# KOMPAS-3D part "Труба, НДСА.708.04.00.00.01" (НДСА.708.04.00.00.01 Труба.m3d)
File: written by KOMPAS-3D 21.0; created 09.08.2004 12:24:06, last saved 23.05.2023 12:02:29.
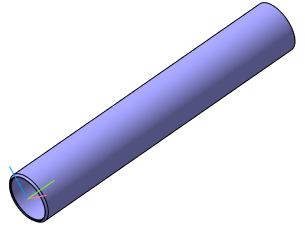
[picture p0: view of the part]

Document properties: Полное имя файла: C:\Users\s.pischagina\Desktop\PLM\НДСА.708.04.00.00.01 Труба.m3d; Автор: Устинов А.В.; Организация: Эсто-вакуум

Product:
- Part/product: Труба  | designation НДСА.708.04.00.00.01
    Материал: Труба$d180х10 ГОСТ 8732-78;20 ГОСТ 8731-74$ (density 7859 kg/m3)
    Масса: 46.57347
    additional columns: <item xmlns="http://appius.ru/pdm" xmlns:xs="http://www.w3.org/2001/XMLSchema" x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; <item xmlns="http://appius.ru/pdm" xmlns:xs="http://www.w3.org/2001/XMLSchema" x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; <item xmlns="http://appius.ru/pdm" xmlns:xs="http://www.w3.org/2001/XMLSchema" x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; <item xmlns="http://appius.ru/pdm" xmlns:xs="http://www.w3.org/2001/XMLSchema" x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; <item xmlns="http://appius.ru/pdm" xmlns:xs="http://www.w3.org/2001/XMLSchema" x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; <item xmlns="http://appius.ru/pdm" xmlns:xs="http://www.w3.org/2001/XMLSchema" x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

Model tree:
1. Плоскость XY
2. Плоскость ZX
3. Плоскость ZY
4. Начало координат
5. Эскиз:1
6. Операция выдавливания:1
     Расстояние 1 = 1113
7. Эскиз:2  (labels: Операция выдавливания:1; Операция выдавливания:1)
8. Вырезать элемент выдавливания:1
     Расстояние 2 = 4.5
9. Фаска:1  (labels: Операция выдавливания:1)
     Угол = 45; Длина 1 = 7; Длина 2 = 7
10. Эскиз:14
11. Вырезать элемент выдавливания:14  (labels: Труба$d180х10 ГОСТ 8732-78;20 ГОСТ 8731-74$)
     Расстояние 1 = 90

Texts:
  НДСА.708.04.00.00.01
